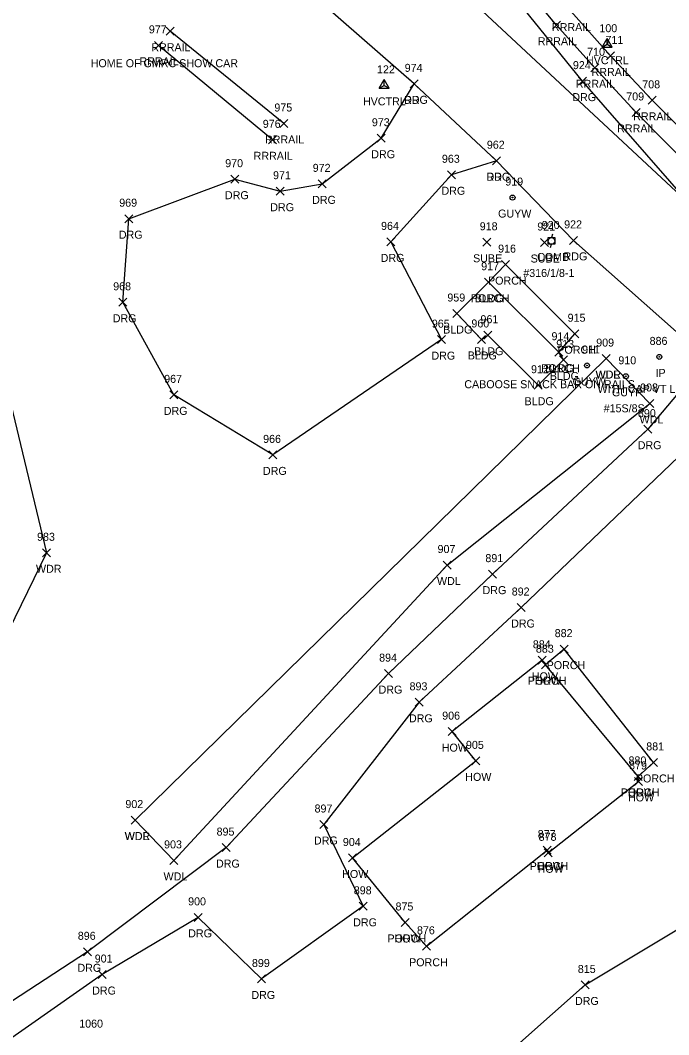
# Model space of a CAD drawing. Extents: x 1615599 to 1619911, y 273782 to 280437.
# Drawn here: x 1616311.5 to 1616473.7, y 279589.5 to 279843.1 of the extents above; entities that cross this region are included whole.
import ezdxf

# ---------------------------------------------------------------- set-up
doc = ezdxf.new("R2010")
doc.units = 0
for name, color, linetype in [('C_A', 7, 'Continuous'), ('C_I', 7, 'Continuous'), ('CPSM', 7, 'Continuous'), ('L_A', 7, 'Continuous'), ('L_C', 7, 'Continuous'), ('L_I', 7, 'Continuous'), ('L_TIC', 7, 'Continuous'), ('LAWA', 7, 'Continuous'), ('LBC', 7, 'Continuous'), ('LBF', 7, 'Continuous'), ('M_A', 7, 'Continuous'), ('M_C', 7, 'Continuous'), ('M_I', 7, 'Continuous'), ('MPIR', 7, 'Continuous'), ('P_A', 7, 'Continuous'), ('P_I', 7, 'Continuous'), ('P_TIC', 7, 'Continuous'), ('PEU', 7, 'Continuous'), ('R_A', 7, 'Continuous'), ('R_C', 7, 'Continuous'), ('R_I', 7, 'Continuous'), ('R_TIC', 7, 'Continuous'), ('RDG', 7, 'Continuous'), ('RR', 7, 'Continuous'), ('U_A', 7, 'Continuous'), ('U_C', 7, 'Continuous'), ('U_I', 7, 'Continuous'), ('U_TIC', 7, 'Continuous'), ('UP', 7, 'Continuous'), ('UPGW', 7, 'Continuous')]:
    doc.layers.add(name, color=color, linetype=linetype)

msp = doc.modelspace()

# ---------------------------------------------------------------- linework, layer by layer
at = {"layer": 'CPSM'}
for p, q in [((1616457.05, 279836.41), (1616458.3, 279838.57)), ((1616459.55, 279836.41), (1616458.3, 279838.57)), ((1616458.3, 279837.13), (1616458.3, 279838.57)), ((1616457.05, 279836.41), (1616458.3, 279837.13)), ((1616457.05, 279836.41), (1616459.55, 279836.41)), ((1616458.3, 279837.13), (1616458.3, 279837.13)), ((1616458.3, 279837.13), (1616459.55, 279836.41)), ((1616401.27, 279826.12), (1616402.52, 279828.28)), ((1616403.77, 279826.12), (1616402.52, 279828.28)), ((1616402.52, 279826.84), (1616402.52, 279828.28)), ((1616401.27, 279826.12), (1616402.52, 279826.84)), ((1616401.27, 279826.12), (1616403.77, 279826.12)), ((1616402.52, 279826.84), (1616402.52, 279826.84)), ((1616402.52, 279826.84), (1616403.77, 279826.12))]:
    msp.add_line(p, q, dxfattribs=at)
at = {"layer": 'L_TIC'}
for points in [[(1616431.87, 279781.03), (1616433.87, 279783.03)], [(1616433.87, 279781.03), (1616431.87, 279783.03)], [(1616427.58, 279776.62), (1616429.58, 279778.62)], [(1616429.58, 279776.62), (1616427.58, 279778.62)], [(1616427.58, 279776.62), (1616429.58, 279778.62)], [(1616429.58, 279776.62), (1616427.58, 279778.62)], [(1616419.69, 279768.8), (1616421.69, 279770.8)], [(1616421.69, 279768.8), (1616419.69, 279770.8)], [(1616427.45, 279763.38), (1616429.45, 279765.38)], [(1616429.45, 279763.38), (1616427.45, 279765.38)], [(1616427.45, 279763.38), (1616429.45, 279765.38)], [(1616429.45, 279763.38), (1616427.45, 279765.38)], [(1616449.19, 279763.75), (1616451.19, 279765.75)], [(1616451.19, 279763.75), (1616449.19, 279765.75)], [(1616425.83, 279762.32), (1616427.83, 279764.32)], [(1616427.83, 279762.32), (1616425.83, 279764.32)], [(1616445.17, 279759.13), (1616447.17, 279761.13)], [(1616447.17, 279759.13), (1616445.17, 279761.13)], [(1616445.17, 279759.13), (1616447.17, 279761.13)], [(1616447.17, 279759.13), (1616445.17, 279761.13)], [(1616457, 279757.54), (1616459, 279759.54)], [(1616459, 279757.54), (1616457, 279759.54)], [(1616457, 279757.54), (1616459, 279759.54)], [(1616459, 279757.54), (1616457, 279759.54)], [(1616446.35, 279757.19), (1616448.35, 279759.19)], [(1616448.35, 279757.19), (1616446.35, 279759.19)], [(1616440.05, 279750.88), (1616442.05, 279752.88)], [(1616442.05, 279750.88), (1616440.05, 279752.88)], [(1616440.05, 279750.88), (1616442.05, 279752.88)], [(1616442.05, 279750.88), (1616440.05, 279752.88)], [(1616467.97, 279746.31), (1616469.97, 279748.31)], [(1616469.97, 279746.31), (1616467.97, 279748.31)], [(1616317.08, 279708.99), (1616319.08, 279710.99)], [(1616319.08, 279708.99), (1616317.08, 279710.99)], [(1616417.31, 279705.93), (1616419.31, 279707.93)], [(1616419.31, 279705.93), (1616417.31, 279707.93)], [(1616446.54, 279684.9), (1616448.54, 279686.9)], [(1616448.54, 279684.9), (1616446.54, 279686.9)], [(1616441.06, 279682.11), (1616443.06, 279684.11)], [(1616443.06, 279682.11), (1616441.06, 279684.11)], [(1616441.83, 279681.01), (1616443.83, 279683.01)], [(1616443.83, 279681.01), (1616441.83, 279683.01)], [(1616441.83, 279681.01), (1616443.83, 279683.01)], [(1616443.83, 279681.01), (1616441.83, 279683.01)], [(1616418.53, 279664.28), (1616420.53, 279666.28)], [(1616420.53, 279664.28), (1616418.53, 279666.28)], [(1616418.53, 279664.28), (1616420.53, 279666.28)], [(1616420.53, 279664.28), (1616418.53, 279666.28)], [(1616424.41, 279656.97), (1616426.41, 279658.97)], [(1616426.41, 279656.97), (1616424.41, 279658.97)], [(1616468.85, 279656.58), (1616470.85, 279658.58)], [(1616470.85, 279656.58), (1616468.85, 279658.58)], [(1616465.08, 279653.08), (1616467.08, 279655.08)], [(1616467.08, 279653.08), (1616465.08, 279655.08)], [(1616465.08, 279653.08), (1616467.08, 279655.08)], [(1616467.08, 279653.08), (1616465.08, 279655.08)], [(1616465.13, 279651.83), (1616467.13, 279653.83)], [(1616467.13, 279651.83), (1616465.13, 279653.83)], [(1616339.24, 279642.17), (1616341.24, 279644.17)], [(1616341.24, 279642.17), (1616339.24, 279644.17)], [(1616339.24, 279642.17), (1616341.24, 279644.17)], [(1616341.24, 279642.17), (1616339.24, 279644.17)], [(1616442.29, 279634.66), (1616444.29, 279636.66)], [(1616444.29, 279634.66), (1616442.29, 279636.66)], [(1616442.29, 279634.66), (1616444.29, 279636.66)], [(1616444.29, 279634.66), (1616442.29, 279636.66)], [(1616442.51, 279633.99), (1616444.51, 279635.99)], [(1616444.51, 279633.99), (1616442.51, 279635.99)], [(1616348.92, 279632.09), (1616350.92, 279634.09)], [(1616350.92, 279632.09), (1616348.92, 279634.09)], [(1616393.63, 279632.69), (1616395.63, 279634.69)], [(1616395.63, 279632.69), (1616393.63, 279634.69)], [(1616406.73, 279616.57), (1616408.73, 279618.57)], [(1616408.73, 279616.57), (1616406.73, 279618.57)], [(1616406.73, 279616.57), (1616408.73, 279618.57)], [(1616408.73, 279616.57), (1616406.73, 279618.57)], [(1616412.13, 279610.62), (1616414.13, 279612.62)], [(1616414.13, 279610.62), (1616412.13, 279612.62)]]:
    msp.add_lwpolyline(points, dxfattribs=at)
at = {"layer": 'LAWA'}
for points in [[(1616265.14, 279867.4), (1616297.18, 279873), (1616303.58, 279770.02), (1616318.08, 279709.99), (1616283.21, 279638.62)], [(1616340.24, 279643.17), (1616349.92, 279633.09), (1616418.31, 279706.93), (1616468.97, 279747.31), (1616458, 279758.54)], [(1616340.24, 279643.17), (1616458, 279758.54)]]:
    msp.add_lwpolyline(points, dxfattribs=at)
at = {"layer": 'LBC'}
for points in [[(1616441.05, 279751.88), (1616447.35, 279758.19), (1616446.17, 279760.13), (1616428.58, 279777.62), (1616420.69, 279769.8), (1616426.83, 279763.32), (1616428.45, 279764.38)], [(1616441.05, 279751.88), (1616428.45, 279764.38)], [(1616443.29, 279635.66), (1616443.51, 279634.99), (1616466.13, 279652.83), (1616466.08, 279654.08), (1616442.83, 279682.01), (1616442.06, 279683.11), (1616419.53, 279665.28)], [(1616407.73, 279617.57), (1616394.63, 279633.69), (1616425.41, 279657.97), (1616419.53, 279665.28)]]:
    msp.add_lwpolyline(points, dxfattribs=at)
at = {"layer": 'LBF'}
for points in [[(1616446.17, 279760.13), (1616450.19, 279764.75), (1616432.87, 279782.03), (1616428.58, 279777.62)], [(1616466.08, 279654.08), (1616469.85, 279657.58), (1616447.54, 279685.9), (1616442.83, 279682.01)], [(1616407.73, 279617.57), (1616413.13, 279611.62), (1616443.29, 279635.66)]]:
    msp.add_lwpolyline(points, dxfattribs=at)
at = {"layer": 'MPIR'}
for radius in [0.625, 0.0833]:
    msp.add_circle((1616471.33, 279758.96), radius, dxfattribs=at)
at = {"layer": 'P_TIC'}
for points in [[(1616409.01, 279826.22), (1616411.01, 279828.22)], [(1616411.01, 279826.22), (1616409.01, 279828.22)], [(1616429.61, 279807), (1616431.61, 279809)], [(1616431.61, 279807), (1616429.61, 279809)], [(1616448.89, 279787.09), (1616450.89, 279789.09)], [(1616450.89, 279787.09), (1616448.89, 279789.09)]]:
    msp.add_lwpolyline(points, dxfattribs=at)
at = {"layer": 'PEU'}
for points in [[(1616499.74, 279780.98), (1616479.11, 279797), (1616319.46, 279945.62), (1616274.32, 279994.35), (1616255.18, 280018.22), (1616235.11, 280063.13), (1616219.63, 280113.45), (1616199.45, 280157.82), (1616176.87, 280194.27), (1616140.8, 280248.09)], [(1616486.88, 279757.56), (1616476.4, 279764.58), (1616449.89, 279788.09), (1616430.61, 279808), (1616410.01, 279827.22), (1616355.68, 279874.73), (1616329.14, 279895.83), (1616251.77, 279973.13), (1616240.04, 279993.6), (1616211.88, 280076.79), (1616204.14, 280097.8), (1616191.71, 280134.04), (1616179.76, 280157.24), (1616153.69, 280197.29), (1616148.4, 280204.31)]]:
    msp.add_lwpolyline(points, dxfattribs=at)
at = {"layer": 'R_TIC'}
for points in [[(1616347.99, 279839.38), (1616349.99, 279841.38)], [(1616349.99, 279839.38), (1616347.99, 279841.38)], [(1616444.64, 279840.88), (1616446.64, 279842.88)], [(1616446.64, 279840.88), (1616444.64, 279842.88)], [(1616345.04, 279835.84), (1616347.04, 279837.84)], [(1616347.04, 279835.84), (1616345.04, 279837.84)], [(1616458.09, 279833.19), (1616460.09, 279835.19)], [(1616460.09, 279833.19), (1616458.09, 279835.19)], [(1616454.17, 279830.23), (1616456.17, 279832.23)], [(1616456.17, 279830.23), (1616454.17, 279832.23)], [(1616409.01, 279826.22), (1616411.01, 279828.22)], [(1616411.01, 279826.22), (1616409.01, 279828.22)], [(1616451.08, 279826.9), (1616453.08, 279828.9)], [(1616453.08, 279826.9), (1616451.08, 279828.9)], [(1616468.51, 279822.1), (1616470.51, 279824.1)], [(1616470.51, 279822.1), (1616468.51, 279824.1)], [(1616464.51, 279819.07), (1616466.51, 279821.07)], [(1616466.51, 279819.07), (1616464.51, 279821.07)], [(1616376.42, 279816.31), (1616378.42, 279818.31)], [(1616378.42, 279816.31), (1616376.42, 279818.31)], [(1616373.57, 279812.23), (1616375.57, 279814.23)], [(1616375.57, 279812.23), (1616373.57, 279814.23)], [(1616400.8, 279812.62), (1616402.8, 279814.62)], [(1616402.8, 279812.62), (1616400.8, 279814.62)], [(1616429.61, 279807), (1616431.61, 279809)], [(1616431.61, 279807), (1616429.61, 279809)], [(1616418.37, 279803.49), (1616420.37, 279805.49)], [(1616420.37, 279803.49), (1616418.37, 279805.49)], [(1616364.21, 279802.39), (1616366.21, 279804.39)], [(1616366.21, 279802.39), (1616364.21, 279804.39)], [(1616386.01, 279801.22), (1616388.01, 279803.22)], [(1616388.01, 279801.22), (1616386.01, 279803.22)], [(1616375.53, 279799.38), (1616377.53, 279801.38)], [(1616377.53, 279799.38), (1616375.53, 279801.38)], [(1616337.67, 279792.51), (1616339.67, 279794.51)], [(1616339.67, 279792.51), (1616337.67, 279794.51)], [(1616403.15, 279786.71), (1616405.15, 279788.71)], [(1616405.15, 279786.71), (1616403.15, 279788.71)], [(1616336.15, 279771.61), (1616338.15, 279773.61)], [(1616338.15, 279771.61), (1616336.15, 279773.61)], [(1616415.85, 279762.27), (1616417.85, 279764.27)], [(1616417.85, 279762.27), (1616415.85, 279764.27)], [(1616348.91, 279748.47), (1616350.91, 279750.47)], [(1616350.91, 279748.47), (1616348.91, 279750.47)], [(1616467.44, 279739.89), (1616469.44, 279741.89)], [(1616469.44, 279739.89), (1616467.44, 279741.89)], [(1616373.71, 279733.46), (1616375.71, 279735.46)], [(1616375.71, 279733.46), (1616373.71, 279735.46)], [(1616428.63, 279703.65), (1616430.63, 279705.65)], [(1616430.63, 279703.65), (1616428.63, 279705.65)], [(1616435.78, 279695.31), (1616437.78, 279697.31)], [(1616437.78, 279695.31), (1616435.78, 279697.31)], [(1616402.63, 279678.78), (1616404.63, 279680.78)], [(1616404.63, 279678.78), (1616402.63, 279680.78)], [(1616410.24, 279671.61), (1616412.24, 279673.61)], [(1616412.24, 279671.61), (1616410.24, 279673.61)], [(1616386.47, 279641.06), (1616388.47, 279643.06)], [(1616388.47, 279641.06), (1616386.47, 279643.06)], [(1616361.98, 279635.29), (1616363.98, 279637.29)], [(1616363.98, 279635.29), (1616361.98, 279637.29)], [(1616396.28, 279620.61), (1616398.28, 279622.61)], [(1616398.28, 279620.61), (1616396.28, 279622.61)], [(1616355.02, 279617.85), (1616357.02, 279619.85)], [(1616357.02, 279617.85), (1616355.02, 279619.85)], [(1616327.32, 279609.24), (1616329.32, 279611.24)], [(1616329.32, 279609.24), (1616327.32, 279611.24)], [(1616331.01, 279603.55), (1616333.01, 279605.55)], [(1616333.01, 279603.55), (1616331.01, 279605.55)], [(1616370.82, 279602.44), (1616372.82, 279604.44)], [(1616372.82, 279602.44), (1616370.82, 279604.44)], [(1616451.75, 279600.95), (1616453.75, 279602.95)], [(1616453.75, 279600.95), (1616451.75, 279602.95)]]:
    msp.add_lwpolyline(points, dxfattribs=at)
at = {"layer": 'RDG'}
for points in [[(1616479.11, 279797), (1616452.08, 279827.9), (1616424.38, 279862.23), (1616403.84, 279893.76), (1616381.28, 279930.94), (1616358.21, 279967.76), (1616328.46, 279952.33), (1616323.53, 279951.52)], [(1616430.61, 279808), (1616419.37, 279804.49), (1616404.15, 279787.71), (1616416.85, 279763.27), (1616374.71, 279734.46), (1616349.91, 279749.47), (1616337.15, 279772.61), (1616338.67, 279793.51), (1616365.21, 279803.39), (1616376.53, 279800.38), (1616387.01, 279802.22), (1616401.8, 279813.62), (1616410.01, 279827.22)], [(1616476.4, 279764.58), (1616476.92, 279750.96), (1616468.44, 279740.89), (1616429.63, 279704.65), (1616403.63, 279679.78), (1616362.98, 279636.29), (1616328.32, 279610.24), (1616263.33, 279567.8)], [(1616497.87, 279749.53), (1616489.21, 279745.16), (1616480.11, 279737.82), (1616436.78, 279696.31), (1616411.24, 279672.61), (1616387.47, 279642.06), (1616397.28, 279621.61), (1616371.82, 279603.44), (1616356.02, 279618.85), (1616332.01, 279604.55), (1616287.77, 279573.66), (1616275.48, 279563.53), (1616266.66, 279551.67)], [(1616496.49, 279521.23), (1616475.87, 279524.73), (1616446.46, 279536.69), (1616430.6, 279554.8), (1616420.14, 279572.99), (1616452.75, 279601.95), (1616486.09, 279622.02), (1616505.13, 279623.42)]]:
    msp.add_lwpolyline(points, dxfattribs=at)
at = {"layer": 'RR'}
for points in [[(1616578.78, 279727.56), (1616559.36, 279743.25), (1616547.84, 279752.47), (1616532.45, 279765.05), (1616519.03, 279776.56), (1616509.64, 279784.79), (1616496.17, 279796.99), (1616483.02, 279809.54), (1616469.51, 279823.1), (1616459.09, 279834.19), (1616449.19, 279845.4), (1616437.84, 279859.03), (1616423.84, 279877.95), (1616413.56, 279893.5), (1616402.73, 279911.89), (1616392.59, 279930.69), (1616381.25, 279953.2), (1616368.15, 279979.78), (1616347.86, 280021.18)], [(1616575.93, 279723.48), (1616556.08, 279739.45), (1616545.23, 279748.16), (1616531.41, 279759.44), (1616516, 279772.44), (1616507.27, 279780.31), (1616493.17, 279793.09), (1616479.92, 279805.59), (1616465.51, 279820.07), (1616455.17, 279831.23), (1616445.64, 279841.88), (1616433.79, 279856.11), (1616419.63, 279875.14), (1616409.64, 279890.58), (1616398.5, 279909.46), (1616388.61, 279927.52), (1616376.81, 279951.06), (1616363.7, 279977.75), (1616343.37, 280019.21)], [(1616377.42, 279817.31), (1616348.99, 279840.38)], [(1616374.57, 279813.23), (1616346.04, 279836.84)]]:
    msp.add_lwpolyline(points, dxfattribs=at)
at = {"layer": 'U_TIC'}
for points in [[(1616427.22, 279786.61), (1616429.22, 279788.61)], [(1616429.22, 279786.61), (1616427.22, 279788.61)], [(1616441.61, 279786.55), (1616443.61, 279788.55)], [(1616443.61, 279786.55), (1616441.61, 279788.55)]]:
    msp.add_lwpolyline(points, dxfattribs=at)
at = {"layer": 'UP'}
for p, q in [((1616443.55, 279787.11), (1616443.55, 279788.78)), ((1616443.55, 279788.78), (1616445.21, 279788.78)), ((1616444.63, 279789.61), (1616444.38, 279788.78)), ((1616444.38, 279787.94), (1616444.38, 279787.94)), ((1616445.21, 279788.78), (1616445.21, 279787.11)), ((1616445.21, 279787.11), (1616443.55, 279787.11)), ((1616444.13, 279786.28), (1616444.38, 279787.11))]:
    msp.add_line(p, q, dxfattribs=at)
msp.add_circle((1616444.38, 279787.94), 0.833, dxfattribs=at)
at = {"layer": 'UPGW'}
for centre, radius in [((1616434.62, 279798.79), 0.625), ((1616434.62, 279798.79), 0.0833), ((1616453.24, 279756.81), 0.625), ((1616453.24, 279756.81), 0.0833), ((1616462.97, 279754.11), 0.625), ((1616462.97, 279754.11), 0.0833)]:
    msp.add_circle(centre, radius, dxfattribs=at)

# ---------------------------------------------------------------- texts
at = {"layer": 'C_A'}
for p in [(1616452.99, 279832.13), (1616397.22, 279821.84)]:
    msp.add_text('HVCTRL', height=2, dxfattribs=at).set_placement(p)
at = {"layer": 'C_I'}
for s, p in [('100', (1616456.34, 279840.13)), ('122', (1616400.73, 279829.84))]:
    msp.add_text(s, height=2, dxfattribs=at).set_placement(p)
at = {"layer": 'L_A'}
for s, p in [('PORCH', (1616428.49, 279777.03)), ('PORCH', (1616424.2, 279772.62)), ('BLDG', (1616425.17, 279772.62)), ('BLDG', (1616417.28, 279764.8)), ('BLDG', (1616423.42, 279758.32)), ('BLDG', (1616425.04, 279759.38)), ('BLDG', (1616425.04, 279759.38)), ('PORCH', (1616445.82, 279759.75)), ('PORCH', (1616441.79, 279755.13)), ('BLDG', (1616442.76, 279755.13)), ('BLDG', (1616443.94, 279753.19)), ('WDR', (1616455.36, 279753.54)), ('WDL', (1616455.41, 279753.54)), ('BLDG', (1616437.64, 279746.88)), ('BLDG', (1616437.64, 279746.88)), ('WDL', (1616466.39, 279742.31)), ('WDR', (1616315.44, 279704.99)), ('WDL', (1616415.72, 279701.93)), ('PORCH', (1616443.16, 279680.9)), ('PORCH', (1616438.46, 279677.01)), ('HOW', (1616439.45, 279678.11)), ('HOW', (1616440.22, 279677.01)), ('HOW', (1616416.92, 279660.28)), ('HOW', (1616416.92, 279660.28)), ('HOW', (1616422.8, 279652.97)), ('PORCH', (1616465.47, 279652.58)), ('PORCH', (1616461.7, 279649.08)), ('HOW', (1616463.47, 279649.08)), ('HOW', (1616463.51, 279647.83)), ('WDR', (1616337.61, 279638.17)), ('WDL', (1616337.66, 279638.17)), ('PORCH', (1616438.91, 279630.66)), ('HOW', (1616440.68, 279630.66)), ('WDL', (1616347.34, 279628.09)), ('HOW', (1616392.02, 279628.69)), ('HOW', (1616440.9, 279629.99)), ('PORCH', (1616403.35, 279612.57)), ('HOW', (1616405.11, 279612.57)), ('PORCH', (1616408.76, 279606.62))]:
    msp.add_text(s, height=2, dxfattribs=at).set_placement(p)
at = {"layer": 'L_C'}
msp.add_text('CABOOSE SNACK BAR ON RAILS', height=2, dxfattribs=at).set_placement((1616422.56, 279751.13))
at = {"layer": 'L_I'}
for s, p in [('916', (1616431.02, 279785.03)), ('917', (1616426.78, 279780.62)), ('917', (1616426.78, 279780.62)), ('959', (1616418.32, 279772.8)), ('915', (1616448.4, 279767.75)), ('960', (1616424.33, 279766.32)), ('961', (1616426.61, 279767.38)), ('961', (1616426.61, 279767.38)), ('914', (1616444.37, 279763.13)), ('914', (1616444.37, 279763.13)), ('913', (1616445.55, 279761.19)), ('909', (1616455.55, 279761.54)), ('909', (1616455.55, 279761.54)), ('912', (1616439.25, 279754.88)), ('912', (1616439.25, 279754.88)), ('908', (1616466.53, 279750.31)), ('983', (1616315.71, 279712.99)), ('907', (1616415.87, 279709.93)), ('882', (1616445.17, 279688.9)), ('884', (1616439.7, 279686.11)), ('883', (1616440.47, 279685.01)), ('883', (1616440.47, 279685.01)), ('906', (1616417.03, 279668.28)), ('906', (1616417.03, 279668.28)), ('905', (1616422.97, 279660.97)), ('881', (1616468.06, 279660.58)), ('880', (1616463.63, 279657.08)), ('880', (1616463.63, 279657.08)), ('879', (1616463.76, 279655.83)), ('902', (1616337.8, 279646.17)), ('902', (1616337.8, 279646.17)), ('877', (1616440.93, 279638.66)), ('877', (1616440.93, 279638.66)), ('903', (1616347.48, 279636.09)), ('904', (1616392.19, 279636.69)), ('878', (1616441.15, 279637.99)), ('875', (1616405.36, 279620.57)), ('875', (1616405.36, 279620.57)), ('876', (1616410.72, 279614.62)), ('1060', (1616326.25, 279591.28)), ('1060', (1616326.25, 279591.28))]:
    msp.add_text(s, height=2, dxfattribs=at).set_placement(p)
at = {"layer": 'M_A'}
msp.add_text('IP', height=2, dxfattribs=at).set_placement((1616470.38, 279753.96))
at = {"layer": 'M_C'}
msp.add_text('WITH CAP VT LLS715', height=2, dxfattribs=at).set_placement((1616455.88, 279749.96))
at = {"layer": 'M_I'}
msp.add_text('886', height=2, dxfattribs=at).set_placement((1616468.91, 279761.96))
at = {"layer": 'P_A'}
for p in [(1616407.5, 279822.22), (1616428.1, 279803), (1616447.38, 279783.09)]:
    msp.add_text('RDG', height=2, dxfattribs=at).set_placement(p)
at = {"layer": 'P_I'}
for s, p in [('974', (1616407.65, 279830.22)), ('962', (1616428.2, 279811)), ('922', (1616447.53, 279791.09))]:
    msp.add_text(s, height=2, dxfattribs=at).set_placement(p)
at = {"layer": 'R_A'}
for s, p in [('RRRAIL', (1616444.48, 279840.4)), ('RRRAIL', (1616440.93, 279836.88)), ('RRRAIL', (1616344.28, 279835.38)), ('RRRAIL', (1616341.33, 279831.84)), ('RRRAIL', (1616454.39, 279829.19)), ('RRRAIL', (1616450.46, 279826.23)), ('DRG', (1616407.5, 279822.22)), ('DRG', (1616449.57, 279822.9)), ('RRRAIL', (1616464.8, 279818.1)), ('RRRAIL', (1616460.8, 279815.07)), ('RRRAIL', (1616372.71, 279812.31)), ('RRRAIL', (1616369.87, 279808.23)), ('DRG', (1616399.29, 279808.62)), ('DRG', (1616428.1, 279803)), ('DRG', (1616362.7, 279798.39)), ('DRG', (1616416.85, 279799.49)), ('DRG', (1616374.02, 279795.38)), ('DRG', (1616384.5, 279797.22)), ('DRG', (1616336.16, 279788.51)), ('DRG', (1616401.64, 279782.71)), ('DRG', (1616334.64, 279767.61)), ('DRG', (1616414.34, 279758.27)), ('DRG', (1616347.4, 279744.47)), ('DRG', (1616465.93, 279735.89)), ('DRG', (1616372.2, 279729.46)), ('DRG', (1616427.12, 279699.65)), ('DRG', (1616434.27, 279691.31)), ('DRG', (1616401.12, 279674.78)), ('DRG', (1616408.72, 279667.61)), ('DRG', (1616384.96, 279637.06)), ('DRG', (1616360.46, 279631.29)), ('DRG', (1616394.77, 279616.61)), ('DRG', (1616353.51, 279613.85)), ('DRG', (1616325.81, 279605.24)), ('DRG', (1616329.49, 279599.55)), ('DRG', (1616369.31, 279598.44)), ('DRG', (1616450.24, 279596.95))]:
    msp.add_text(s, height=2, dxfattribs=at).set_placement(p)
at = {"layer": 'R_C'}
msp.add_text('HOME OF GMRC SHOW CAR', height=2, dxfattribs=at).set_placement((1616329.12, 279831.38))
at = {"layer": 'R_I'}
for s, p in [('977', (1616343.67, 279839.84)), ('711', (1616457.87, 279837.19)), ('710', (1616453.28, 279834.23)), ('924', (1616449.72, 279830.9)), ('974', (1616407.65, 279830.22)), ('708', (1616467.07, 279826.1)), ('709', (1616463.06, 279823.07)), ('975', (1616375.06, 279820.31)), ('976', (1616372.16, 279816.23)), ('973', (1616399.44, 279816.62)), ('962', (1616428.2, 279811)), ('970', (1616362.76, 279806.39)), ('963', (1616416.96, 279807.49)), ('971', (1616374.73, 279803.38)), ('972', (1616384.65, 279805.22)), ('969', (1616336.26, 279796.51)), ('964', (1616401.74, 279790.71)), ('968', (1616334.75, 279775.61)), ('965', (1616414.44, 279766.27)), ('967', (1616347.5, 279752.47)), ('890', (1616465.99, 279743.89)), ('966', (1616372.25, 279737.46)), ('891', (1616427.83, 279707.65)), ('892', (1616434.42, 279699.31)), ('894', (1616401.26, 279682.78)), ('893', (1616408.87, 279675.61)), ('897', (1616385.11, 279645.06)), ('895', (1616360.61, 279639.29)), ('898', (1616394.92, 279624.61)), ('900', (1616353.49, 279621.85)), ('896', (1616325.9, 279613.24)), ('901', (1616330.13, 279607.55)), ('899', (1616369.45, 279606.44)), ('815', (1616450.95, 279604.95))]:
    msp.add_text(s, height=2, dxfattribs=at).set_placement(p)
at = {"layer": 'U_A'}
for s, p in [('GUYW', (1616431.01, 279793.79)), ('COMB', (1616440.76, 279782.94)), ('SUBE', (1616424.75, 279782.61)), ('SUBE', (1616439.15, 279782.55)), ('GUYW', (1616449.64, 279751.81)), ('GUYP', (1616459.48, 279749.11))]:
    msp.add_text(s, height=2, dxfattribs=at).set_placement(p)
at = {"layer": 'U_C'}
for s, p in [('#316/1/8-1', (1616437.31, 279778.94)), ('#15S/8S', (1616457.41, 279745.11))]:
    msp.add_text(s, height=2, dxfattribs=at).set_placement(p)
at = {"layer": 'U_I'}
for s, p in [('919', (1616432.81, 279801.79)), ('918', (1616426.42, 279790.61)), ('921', (1616440.82, 279790.55)), ('920', (1616441.93, 279790.94)), ('911', (1616452.02, 279759.81)), ('910', (1616461.09, 279757.11))]:
    msp.add_text(s, height=2, dxfattribs=at).set_placement(p)

doc.saveas('drawing.dxf')
